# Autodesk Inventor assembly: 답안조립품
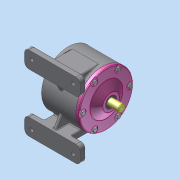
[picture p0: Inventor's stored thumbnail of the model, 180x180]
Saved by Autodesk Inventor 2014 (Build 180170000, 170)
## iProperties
Created: 2026-04
Part Number: 답안조립품
Document SubType Name: Assembly
Designer: dg
Mass: 8639.91 g
Surface Area: 4931.16 cm^2
Volume: 2694.43 cm^3
Density: 3.20659 g/cm^3
Author: dg
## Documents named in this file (17)
- C:\Users\dg\Desktop\660403V1008\답안조립품.iam
- C:\Users\dg\Desktop\660403V1008\가져온 구성요소\본체\본체.ipt
- C:\Users\dg\Desktop\660403V1008\가져온 구성요소\C형 멈춤링 구멍용 42\C형 멈춤링 구멍용 42.ipt
- C:\Users\dg\Desktop\660403V1008\가져온 구성요소\기어 축\기어 축.ipt
- C:\Users\dg\Desktop\660403V1008\가져온 구성요소\깊은 홈 볼 베어링 6004\깊은 홈 볼 베어링 6004.ipt
- C:\Users\dg\Desktop\660403V1008\가져온 구성요소\평행 키 6x6x16\평행 키 6x6x16.ipt
- C:\Users\dg\Desktop\660403V1008\가져온 구성요소\6각 구멍붙이 볼트 M4x10\6각 구멍붙이 볼트 M4x10.ipt
- C:\Users\dg\Desktop\660403V1008\가져온 구성요소\구동 기어\구동 기어.ipt
- C:\Users\dg\Desktop\660403V1008\가져온 구성요소\엔드 캡\엔드 캡.ipt
- C:\Users\dg\Desktop\660403V1008\가져온 구성요소\칼라 1\칼라 1.ipt
- C:\Users\dg\Desktop\660403V1008\가져온 구성요소\6각 머리 볼트 M8x20\6각 머리 볼트 M8x20.ipt
- C:\Users\dg\Desktop\660403V1008\가져온 구성요소\오일 실 25 40 8\오일 실 25 40 8.ipt
- C:\Users\dg\Desktop\660403V1008\가져온 구성요소\커버\커버.ipt
- C:\Users\dg\Desktop\660403V1008\가져온 구성요소\깊은 홈 볼 베어링 6005\깊은 홈 볼 베어링 6005.ipt
- C:\Users\dg\Desktop\660403V1008\가져온 구성요소\종동 기어\종동 기어.ipt
- C:\Users\dg\Desktop\660403V1008\가져온 구성요소\출력 축\출력 축.ipt
- C:\Users\dg\Desktop\660403V1008\가져온 구성요소\칼라 2\칼라 2.ipt
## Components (9 placed, 4 different names)
1. C형 멈춤링 구멍용 42:1
2. 6각 구멍붙이 볼트 M4x10:1
3. 구동 기어:1
4. 6각 머리 볼트 M8x20:1
5. 6각 머리 볼트 M8x20:2
6. 6각 머리 볼트 M8x20:3
7. 6각 머리 볼트 M8x20:4
8. 6각 머리 볼트 M8x20:5
9. 6각 머리 볼트 M8x20:6
